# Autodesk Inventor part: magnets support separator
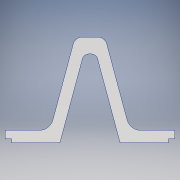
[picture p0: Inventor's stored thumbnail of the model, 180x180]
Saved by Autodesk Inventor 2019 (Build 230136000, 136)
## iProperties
Created: 2019-05
Part Number: magnets support separator
Material: Aluminum 6061
Document SubType Name: Modeling
Designer: Chloe
Density: 2.7 g/cm^3
Appearance: Aluminum - Flat
Author: Chloe
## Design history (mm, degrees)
sketch "Sketch1"
  geometry: L1 (0, 0)-(80, 0); L2 (80, 0)-(80, -6); L3 (80, -6)-(0, -6); L4 (0, -6)-(0, 0); L5 (40, -6)-(40, 69.854); L6 (40, -6)-(115.854, -6); L7 (40, 47.07)-(25.78, -6); L8 (40, 47.07)-(54.22, -6); L9 (40, 70.252)-(19.568, -6); L10 (40, 70.252)-(60.432, -6); L11 (32.966, 44)-(47.034, 44); L12 (30.822, 36)-(49.178, 36); L13 (0, -4)-(3, -4); L14 (3, -4)-(3, -6); L15 (3, -6)-(0, -6); L16 (0, -6)-(0, -4); L17 (80, -6)-(77, -6); L18 (77, -6)-(77, -4); L19 (77, -4)-(80, -4); L20 (80, -4)-(80, -6)
  constraints: 40 end point, 11 point on line, 9 parallel, 5 horizontal, 4 perpendicular, 1 midpoint
  dimensions: "d0" = 80 distance of L2.end L3.end; "d1" = 6 distance of L1.end L2.end; "d2" = 90 deg angle of L6 L5; "d3" = 15 deg angle of L5 L7; "d4" = 15 deg angle of L5 L8 (= d3); "d5" = 25.78 distance from line of L4 L7.end; "d6" = 25.78 distance from line of L2 L8.end (derived); "d7" = 6 distance between parallel lines of L9 L7; "d8" = 50 distance between parallel lines of L3 L11; "d9" = 8 distance between parallel lines of L12 L11; "d10" = 3 distance of L14.end L15.end; "d11" = 2 distance of L13.end L14.end; "d12" = 0 distance between parallel lines of L3 L15; "d13" = 3 distance of L18.end L19.end; "d14" = 2 distance between parallel lines of L19 L17
sketch "Sketch3"
  geometry: L1 (40, 70.252)-(19.568, -6) reference; L2 (40, 70.252)-(60.432, -6) reference; L3 (32.966, 44)-(47.034, 44) reference; L4 (30.822, 36)-(49.178, 36) reference; L5 (40, 47.07)-(25.78, -6) reference; L6 (40, 47.07)-(54.22, -6) reference; L7 (0, 0)-(80, 0) reference; L8 (0, -6)-(0, 0) reference; L9 (80, -6)-(0, -6) reference; L10 (80, 0)-(80, -6) reference; L11 (77, -6)-(77, -4) reference; L12 (77, -4)-(80, -4) reference; L13 (0, -4)-(3, -4) reference; L14 (3, -4)-(3, -6) reference; L15 (32.966, 44)-(47.034, 44); L16 (58.824, 0)-(80, 0); L17 (32.966, 44)-(47.034, 44); L18 (58.824, 0)-(80, 0); L19 (80, -4)-(77, -4); L20 (3, -4)-(0, -4); L21 (0, 0)-(21.176, 0); L22 (32.966, 44)-(21.176, 0); L23 (0, 0)-(0, -4); L24 (3, -4)-(3, -6); L25 (80, 0)-(80, -4); L26 (77, -4)-(77, -6); L27 (47.034, 44)-(58.824, 0); L28 (37.034, 36)-(42.966, 36); L29 (37.034, 36)-(25.78, -6); L30 (25.78, -6)-(3, -6); L31 (42.966, 36)-(54.22, -6); L32 (54.22, -6)-(77, -6); 1 further point
  constraints: 36 end point, 9 collinear, 8 point on line, 2 parallel, 1 perpendicular
extrude "Extrusion1" new body sketch "Sketch3" distance "d15" = 29.08; taper "d16" = 0 deg
fillet "Fillet3" dims "d19" = 6.54, "d20" = 4.5, "d21" = 3
sketch "Sketch4"
  geometry: L1 (0, -2)-(-29.08, -2) reference; L2 (0, -2)-(-29.08, -2); L3 (-29.08, -2)-(-29.08, 48); L4 (-29.08, 48)-(0, 48); L5 (0, 48)-(0, -2); L6 (0, 48)-(-29.08, 48) reference; L7 (-29.08, 8.847)-(-29.08, 44.665) reference; L8 (-14.54, -2)-(-14.54, 69.573); L9 (-14.54, -2)-(57.033, -2); L10 (-17.578, 48)-(-29.08, -2); L11 (-11.502, 48)-(0, -2); 1 further point
  constraints: 16 end point, 2 horizontal, 2 parallel, 2 perpendicular, 1 midpoint
  dimensions: "d22" = 0 distance between parallel lines of L4 L6; "d23" = 0 distance between parallel lines of L3 L7; "d24" = 90 deg angle of L9 L8; "d25" = 12.955 deg angle of L10 L8; "d26" = 12.955 deg angle of L8 L11 (= d25); "d27" = 0 distance from line of L1 L10.end; "d28" = 0 distance from line of L9 L11.end (computed from d27); "d29" = 0 distance from line of L3 L10.end; "d30" = 0 distance from line of L5 L11.end; "d31" = 0 distance from line of L4 L10.start; "d32" = 0 distance from line of L4 L11.start
sketch "Sketch5"
  geometry: L1 (-17.578, 48)-(-29.08, -2) reference; L2 (0, 48)-(-29.08, 48) reference; L3 (-29.08, -2)-(-29.08, 48) reference; L4 (0, 48)-(0, -2) reference; L5 (-11.502, 48)-(0, -2) reference; 1 further point
extrude "Extrusion2" cut sketch "Sketch5" extent not by distance; stored distance "d33" = 29.08; taper "d34" = 0 deg
sketch "Sketch6"
  geometry: L1 (16.158, 26.32)-(16.158, 0) reference; L2 (-63.842, 26.32)-(-63.842, 0) reference; L3 (-9.622, -1.38)-(13.158, -1.38) reference; L4 (-9.622, 27.7)-(13.158, 27.7) reference; L5 (-60.842, -1.38)-(-38.062, -1.38) reference; L6 (-60.842, 27.7)-(-38.062, 27.7) reference; L7 (0, 0)-(16.158, 0) reference; L8 (-47.685, 26.32)-(-63.842, 26.32) reference; L9 (-63.842, 0)-(-47.685, 0) reference; L10 (16.158, 26.32)-(0, 26.32) reference; 5 further points
  dimensions: "d35" = 10 distance from line of L1 point (6.158, 4.62); "d36" = 10 distance from line of point (6.158, 21.7) L1 (= d35); "d37" = 10 distance from line of L2 point (-53.842, 4.62) (= d35); "d38" = 10 distance from line of L2 point (-53.842, 21.7) (= d35); "d60" = 6 distance from line of L3 point (6.158, 4.62); "d61" = 6 distance from line of L4 point (6.158, 21.7) (= d60); "d62" = 6 distance from line of L6 point (-53.842, 21.7) (= d60); "d63" = 6 distance from line of L5 point (-53.842, 4.62) (= d60)
hole "Hole1" sketch "Sketch6" at (6.158, 4.62), (6.158, 21.7), (-53.842, 4.62), (-53.842, 21.7) diameter "d43" = 3.1; stored, may be unused: countersink angle "d47" = 90 deg, drill point angle "d49" = 118 deg; dims "d44" = 119.9896, "d45" = 4, "d46" = 2, "d48" = 8
sketch "Sketch7"
  geometry: C1 r 1.55 at (-53.842, 4.62) reference; C2 r 1.55 at (-53.842, 21.7) reference; C3 r 1.55 at (6.158, 21.7) reference; C4 r 1.55 at (6.158, 4.62) reference; C5 r 3.25 at (6.158, 4.62); C6 r 3.25 at (6.158, 21.7); C7 r 3.25 at (-53.842, 21.7); C8 r 3.25 at (-53.842, 4.62); 1 further point
  constraints: 4 centre point, 4 coincident
  dimensions: "d50" = 6.5 diameter of C5; "d51" = 6.5 diameter of C6; "d52" = 6.5 diameter of C7; "d53" = 6.5 diameter of C8
extrude "Extrusion3" cut sketch "Sketch7" distance "d54" = 2; taper "d55" = 0 deg
body "Solid1"
